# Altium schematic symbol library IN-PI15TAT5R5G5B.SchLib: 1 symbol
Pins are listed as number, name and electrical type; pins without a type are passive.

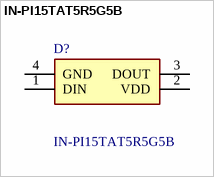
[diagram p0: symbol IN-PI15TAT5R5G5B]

## IN-PI15TAT5R5G5B
designator D?
TOP MOUNT / 1515 / 1.5 X 1.5 X 0; Manufacturer_Name: Inolux; Geometry.Height: 0.75mm
footprint INPI15TAT5R5G5B
pins: 1 DIN, 2 VDD, 3 DOUT, 4 GND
